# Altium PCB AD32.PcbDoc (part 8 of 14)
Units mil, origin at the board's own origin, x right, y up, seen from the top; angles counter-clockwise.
Board outline 7007.87 x 4368.85 mil, 12 copper layers (Top Layer, Int1 (GND), Int2 (AVDD), Int3 (DVDD), Int4 (GND), Int5 (ST), Int6 (SB), Int8 (AGND), Int7 (AVCC), Int9 (VCCA), Int10 (GND), Bottom Layer), stack 60.136 mil thick; 1350 components, 880 nets, 4712 pads, 2835 vias.
Unrouted connection lines stored in the file: 19.
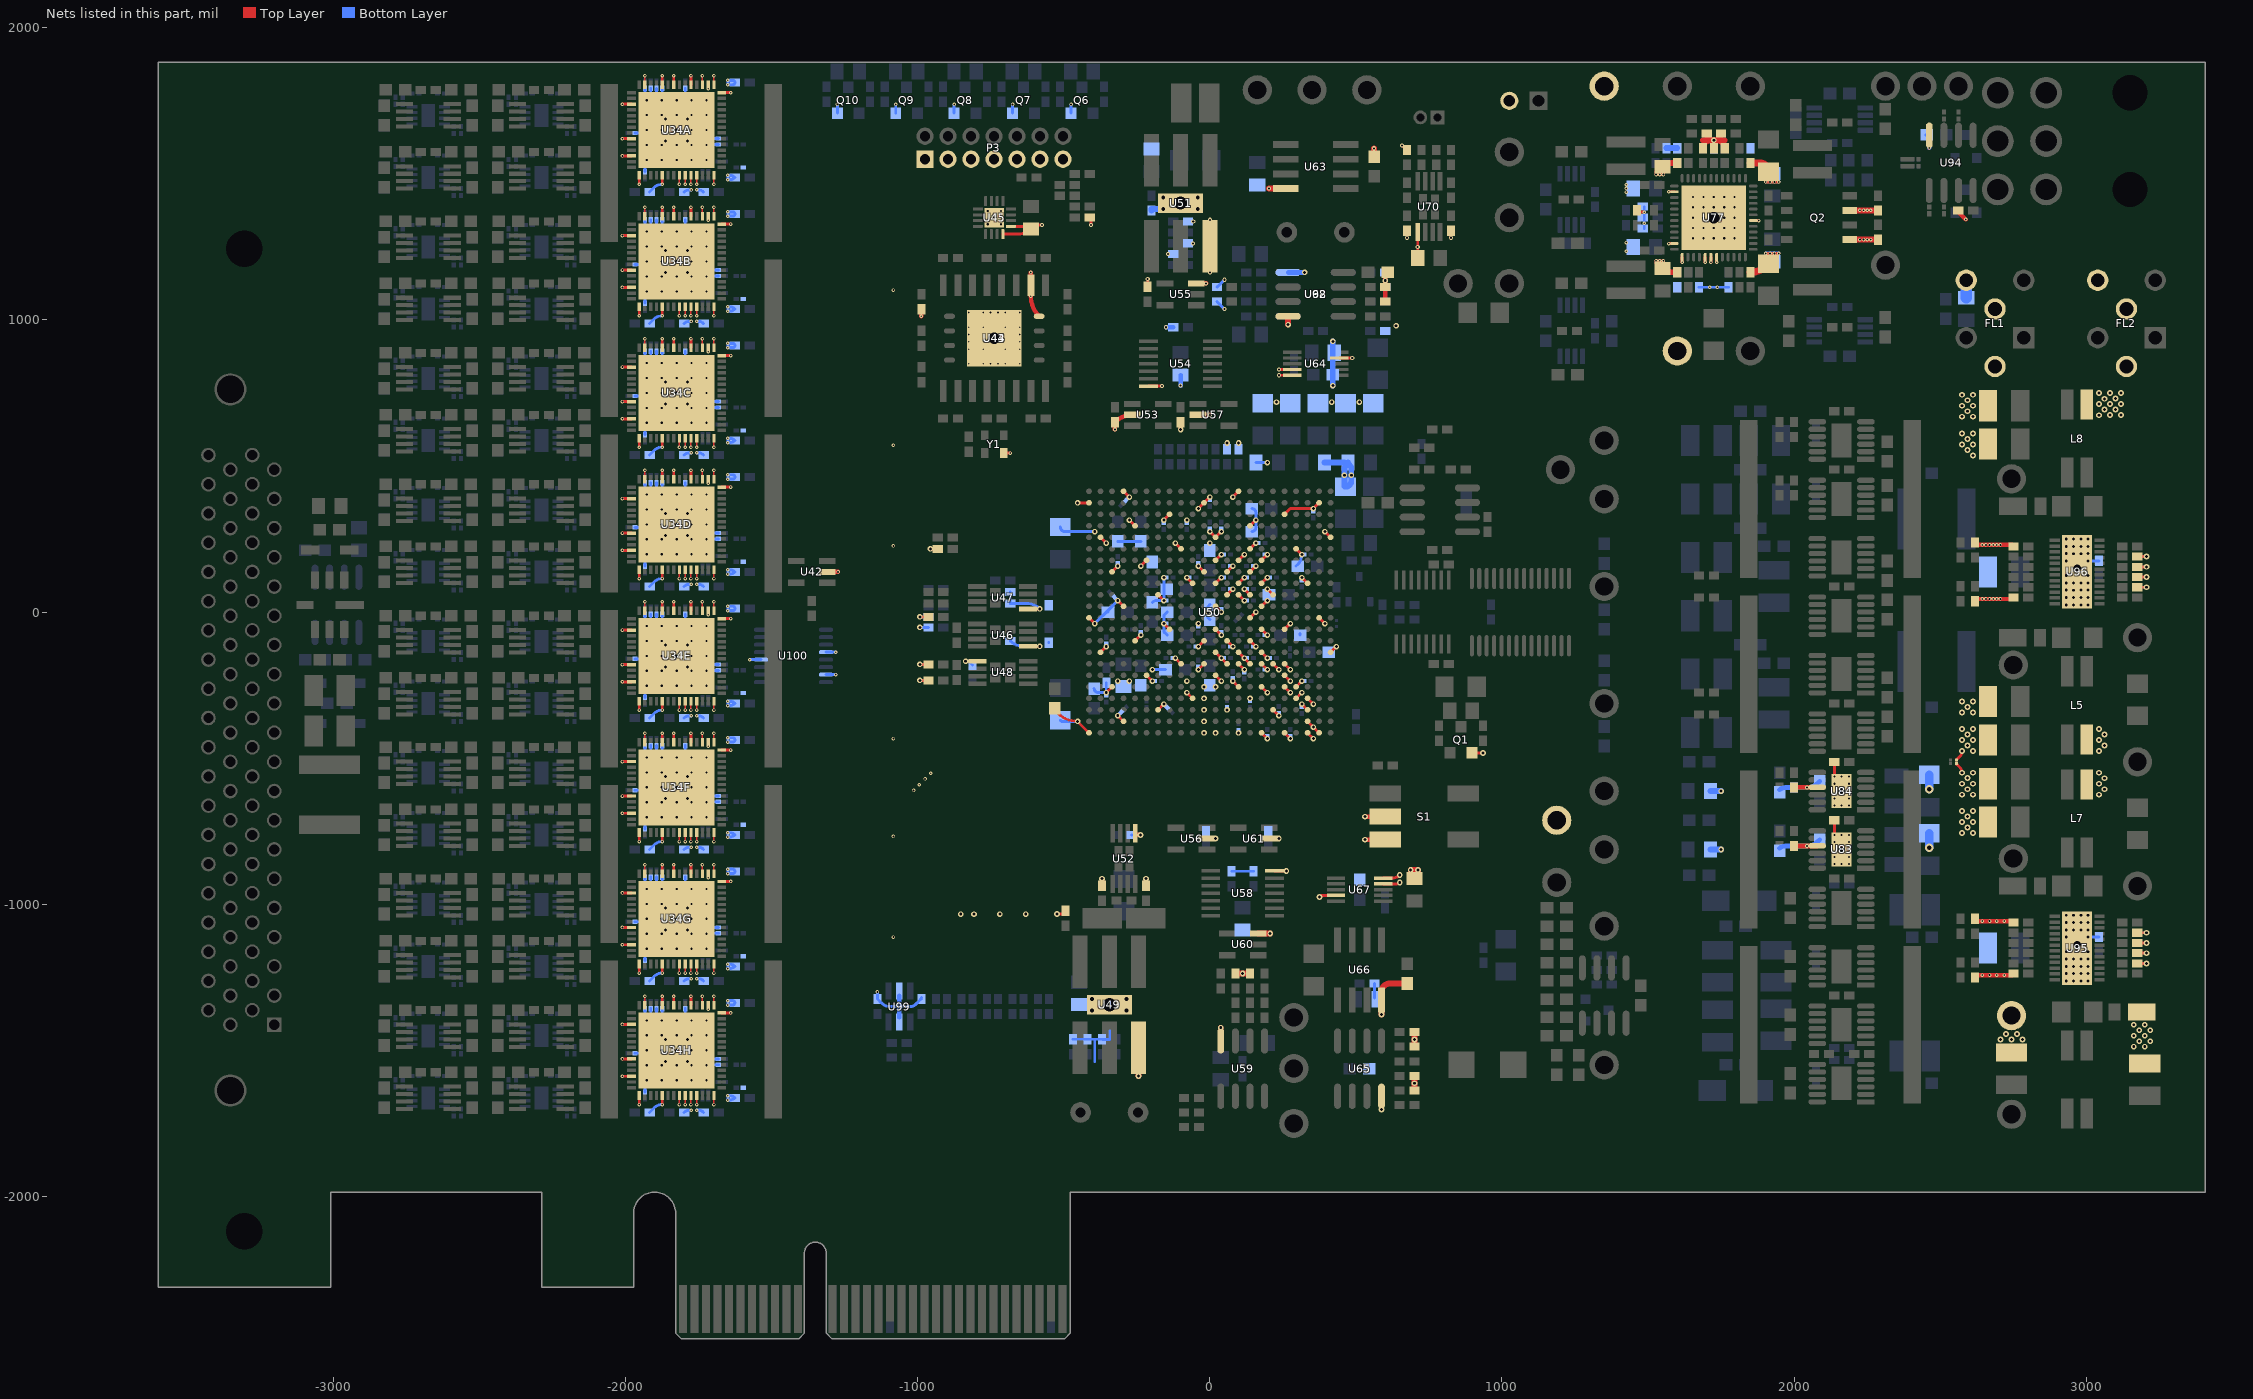
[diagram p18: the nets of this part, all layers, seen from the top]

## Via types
v1: diameter 12, hole 6, Top Layer to Bottom Layer, tented both sides, 1497 vias
v2: diameter 20, hole 10, Top Layer to Bottom Layer, tented both sides, 364 vias
v3: diameter 19, hole 10, Top Layer to Bottom Layer, tented both sides, 347 vias
v4: diameter 14, hole 7, Top Layer to Bottom Layer, tented both sides, 228 vias
v5: diameter 19.68, hole 7.87, Top Layer to Bottom Layer, 225 vias
v6: diameter 19.02, hole 10, Top Layer to Bottom Layer, tented both sides, 85 vias
v7: diameter 20, hole 10, Top Layer to Bottom Layer, 32 vias
v8: diameter 40, hole 20, Top Layer to Bottom Layer, tented both sides, 14 vias
v9: diameter 30, hole 15, Top Layer to Bottom Layer, tented both sides, 12 vias
v10: diameter 25, hole 13, Top Layer to Bottom Layer, 8 vias
v11: diameter 40, hole 20, Top Layer to Bottom Layer, 6 vias
v12: diameter 50, hole 20, Top Layer to Bottom Layer, 6 vias
v13: diameter 66, hole 47, Top Layer to Bottom Layer, tented both sides, 3 vias
v14: diameter 63, hole 45, Top Layer to Bottom Layer, 2 vias
v15: diameter 50, hole 25, Top Layer to Bottom Layer, 2 vias
v16: diameter 12, hole 6, Top Layer to Bottom Layer, 2 vias
v17: diameter 60, hole 40, Top Layer to Bottom Layer, tented both sides, 1 vias
v18: diameter 60, hole 40, Top Layer to Bottom Layer, 1 vias

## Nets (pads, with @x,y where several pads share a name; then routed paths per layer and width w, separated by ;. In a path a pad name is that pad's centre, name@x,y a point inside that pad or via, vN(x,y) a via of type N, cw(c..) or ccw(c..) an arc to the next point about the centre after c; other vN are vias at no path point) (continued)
GND: C5.2 C37.1 C39.1 C40.1 C41.1 C42.1 C44.1 C45.2 C47.1 C48.1 C49.1 C50.1 C51.1 C52.1 C53.1 C54.2 C55.1 C61.1 C64.1 C68.1 C69.1 C70.1 C71.1 C72.2 C73.1 C74.1 C75.1 C76.2 C77.1 C82.2 C83.1 C84.2 C85.1 C86.1 C87.2 C88.1 C89.1 C90.2 C91.2 C92.2 C93.2 C94.2 C95.1 C96.1 C101.1 C102.1 C103.2 C104.2 C105.1 C106.2 C107.2 C110.2 C111.2 C114.1 C115.1 C118.1 C119.1 C124.1 C125.1 C126.2 C127.2 C136.1 C137.2 C138.2 C139.2 C140.1 C148.1 C149.1 C150.1 C152.2 C153.1 C155.2 C156.1 C157.1 C159.1 C160.1 C161.1 C162.2 C164.1 C165.2 C166.1 C167.1 C168.1 C169.1 C170.1 C171.1 C172.2 C173.1 C174.1 C175.1 C176.1 C177.2 C178.2 C179.1 C180.1 C182.1 C183.1 C184.2 C185.1 C187.1 C188.2 C189.2 C190.1 C191.1 C193.2 C194.2 C195.2 C196.2 C197.2 C198.2 C199.2 C200.1 C201.1 C202.2 C203.2 C206.1 C207.1 C208.1 C209.2 C210.2 C211.2 C212.1 C213.1 C214.2 C215.2 C216.1 C217.1 C218.2 C219.2 C220.1 C222.1 C223.1 C224.1 C225.1 C226.1 C227.1 C228.1 C229.1 C230.1 C231.1 C232.1 C233.1 C234.1 C235.1 C236.1 C237.1 C238.1 C239.1 C240.1 C241.2 C242.1 C243.1 C244.1 C245.1 C246.1 C247.1 C248.2 C249.1 C250.1 C251.1 C252.1 C253.1 C254.1 C255.1 C256.1 C257.1 C258.1 C259.1 C260.1 C261.1 C262.2 C263.1 C264.2 C265.1 C266.1 C267.1 C268.1 C269.2 C270.1 C271.1 C272.1 C274.1 C275.1 C282.1 C285.1 C287.2 C288A.2 C288B.2 C288C.2 C288D.2 C288E.2 C288F.2 C288G.2 C288H.2 C289A.2 C289B.2 C289C.2 C289D.2 C289E.2 C289F.2 C289G.2 C289H.2 C304A.2 C304B.2 C304C.2 C304D.2 C304E.2 C304F.2 C304G.2 C304H.2 C312A.2 C312B.2 C312C.2 C312D.2 C312E.2 C312F.2 C312G.2 C312H.2 C320A.2 C320B.2 C320C.2 C320D.2 C320E.2 C320F.2 C320G.2 C320H.2 C328A.2 C328B.2 C328C.2 C328D.2 C328E.2 C328F.2 C328G.2 C328H.2 C336A.2 C336B.2 C336C.2 C336D.2 C336E.2 C336F.2 C336G.2 C336H.2 C344A.2 C344B.2 C344C.2 C344D.2 C344E.2 C344F.2 C344G.2 C344H.2 C352A.2 C352B.2 C352C.2 C352D.2 C352E.2 C352F.2 C352G.2 C352H.2 C360A.2 C360B.2 C360C.2 C360D.2 C360E.2 C360F.2 C360G.2 C360H.2 C361A.2 C361B.2 C361C.2 C361D.2 C361E.2 C361F.2 C361G.2 C361H.2 C383A.1 C383B.1 C383C.1 C383D.1 C383E.1 C383F.1 C383G.1 C383H.1 D8.2 FL1.4 FL1.5 FL1.6 FL2.4 FL2.5 FL2.6 FR10.1 L5.4 L7.3 L8.3 P3.1 P3.3 P3.5 P3.7 P3.9 P3.11 P3.13 P4.2 Q1.2 Q2.1 Q2.3 Q6.2 Q7.2 Q8.2 Q9.2 Q10.2 R135.2 R136.2 R137.1 R138.2 R139.2 R162.1 R165.1 R167.2 R179.2 R182.2 R183.2 R185.2 R219.2 R225.2 R227.2 R241.1 R242.1 R253.1 R254.1 R258.2 R259.2 R285.1 R286.1 R288.2 R291.2 R293.2 R294.2 R295.1 R314.1 R315.1 R324.1 R329.2 R331.2 R336.2 R339.1 R340.1 R341.1 R342.1 R343.2 R365.2 R366.2 R368.2 R376.2 R377.2 R383.2 R384.2 R386.1 R392.2 R395.1 R401A.2 R401B.2 R401C.2 R401D.2 R401E.2 R401F.2 R401G.2 R401H.2 R418A.1 R418B.1 R418C.1 R418D.1 R418E.1 R418F.1 R418G.1 R418H.1 R419A.1 R419B.1 R419C.1 R419D.1 R419E.1 R419F.1 R419G.1 R419H.1 S1.3 S1.5 TP14.1 TP24.1 TP25.1 TP34.1 U34A.14 U34A.15 U34A.16 U34A.17 U34A.19 U34A.22 U34A.24 U34A.27 U34A.31 U34A.37 U34A.40 U34A.43 U34A.47 U34A.50 U34A.51 U34A.52 U34A.53 U34A.56 U34A.57 U34B.14 U34B.15 U34B.16 U34B.17 U34B.19 U34B.22 U34B.24 U34B.27 U34B.31 U34B.37 U34B.40 U34B.43 U34B.47 U34B.50 U34B.51 U34B.52 U34B.53 U34B.56 U34B.57 U34C.14 U34C.15 U34C.16 U34C.17 U34C.19 U34C.22 U34C.24 U34C.27 U34C.31 U34C.37 U34C.40 U34C.43 U34C.47 U34C.50 U34C.51 U34C.52 U34C.53 U34C.56 U34C.57 U34D.14 U34D.15 U34D.16 U34D.17 U34D.19 U34D.22 U34D.24 U34D.27 U34D.31 U34D.37 U34D.40 U34D.43 U34D.47 U34D.50 U34D.51 U34D.52 U34D.53 U34D.56 U34D.57 U34E.14 U34E.15 U34E.16 U34E.17 U34E.19 U34E.22 U34E.24 U34E.27 U34E.31 U34E.37 U34E.40 U34E.43 U34E.47 U34E.50 U34E.51 U34E.52 U34E.53 U34E.56 U34E.57 U34F.14 U34F.15 U34F.16 U34F.17 U34F.19 U34F.22 U34F.24 U34F.27 U34F.31 U34F.37 U34F.40 U34F.43 U34F.47 U34F.50 U34F.51 U34F.52 U34F.53 U34F.56 U34F.57 U34G.14 U34G.15 U34G.16 U34G.17 U34G.19 U34G.22 U34G.24 U34G.27 U34G.31 U34G.37 U34G.40 U34G.43 U34G.47 U34G.50 U34G.51 U34G.52 U34G.53 U34G.56 U34G.57 U34H.14 U34H.15 U34H.16 U34H.17 U34H.19 U34H.22 U34H.24 U34H.27 U34H.31 U34H.37 U34H.40 U34H.43 U34H.47 U34H.50 U34H.51 U34H.52 U34H.53 U34H.56 U34H.57 U42.2 U43.10 U44.4 U44.9 U45.1 U45.16 U45.17 U45.18 U45.19 U45.20 U45.21 U45.22 U46.5 U47.5 U48.5 U49.3 U49.7 U50.A2 U50.A3 U50.A5 U50.A7 U50.A9 U50.A11 U50.A12 U50.A22 U50.AA2 U50.AA12 U50.AA22 U50.AB9 U50.AB19 U50.B3 U50.B12 U50.B19 U50.C3 U50.C6 U50.C10 U50.C12 U50.C16 U50.D3 U50.D4 U50.D8 U50.D12 U50.D13 U50.E4 U50.E5 U50.E7 U50.E9 U50.E11 U50.E12 U50.E20 U50.F5 U50.F11 U50.F17 U50.G5 U50.G6 U50.G7 U50.G8 U50.G9 U50.G10 U50.G12 U50.G14 U50.H1 U50.H7 U50.H9 U50.H11 U50.H21 U50.J8 U50.J10 U50.J12 U50.J18 U50.K5 U50.K7 U50.K11 U50.K15 U50.L2 U50.L8 U50.L22 U50.M7 U50.M11 U50.M19 U50.N6 U50.N8 U50.N9 U50.N10 U50.N16 U50.P3 U50.P7 U50.P9 U50.P11 U50.P13 U50.R8 U50.R10 U50.R12 U50.R20 U50.T7 U50.T9 U50.T11 U50.T17 U50.U4 U50.U8 U50.U14 U50.V1 U50.V11 U50.V21 U50.W8 U50.W18 U50.Y5 U50.Y15 U51.3 U51.7 U52.5 U53.2 U54.7 U55.3 U56.2 U57.2 U58.7 U59.4 U60.3 U61.2 U62.4 U63.4 U64.4 U64.5 U64.9 U65.4 U66.4 U67.4 U67.5 U67.9 U70.5 U77.2 U77.11 U77.13 U77.17 U77.18 U77.19 U77.30 U77.49 U83.9 U83.13 U84.9 U84.13 U94.4 U95.25 U96.25 U98.4 U99.2 U99.5 U100.4 U100.7 U100.12 W1.1 W2.1 Y1.2 | length 34851.7
  Top Layer w5: U34H.27@-1933.27,-1345.38 v1(-1933.27,-1314.57) ; U34G.27@-1933.27,-895.38 v1(-1933.27,-864.57) ; U34F.27@-1933.27,-445.38 v1(-1933.27,-414.57) ; U34E.27@-1933.27,4.62 v1(-1933.27,35.43) ; U34D.27@-1933.27,454.62 v1(-1933.27,485.43) ; U34C.27@-1933.27,904.62 v1(-1933.27,935.43) ; U34B.27@-1933.27,1354.62 v1(-1933.27,1385.43) ; U34A.27@-1933.27,1804.62 v1(-1933.27,1835.43) ; v1(-1815.16,-1685.43) U34H.50@-1815.16,-1654.62 ; v1(-1815.16,-1235.43) U34G.50@-1815.16,-1204.62 ; v1(-1815.16,-785.43) U34F.50@-1815.16,-754.62 ; v1(-1815.16,-335.43) U34E.50@-1815.16,-304.62 ; v1(-1815.16,114.57) U34D.50@-1815.16,145.38 ; v1(-1815.16,564.57) U34C.50@-1815.16,595.38 ; v1(-1815.16,1014.57) U34B.50@-1815.16,1045.38 ; v1(-1815.16,1464.57) U34A.50@-1815.16,1495.38 ; v1(-1795.47,-1685.43) U34H.51@-1795.47,-1654.62 ; v1(-1795.47,-1235.43) U34G.51@-1795.47,-1204.62 ; v1(-1795.47,-785.43) U34F.51@-1795.47,-754.62 ; v1(-1795.47,-335.43) U34E.51@-1795.47,-304.62 ; v1(-1795.47,114.57) U34D.51@-1795.47,145.38 ; v1(-1795.47,564.57) U34C.51@-1795.47,595.38 ; v1(-1795.47,1014.57) U34B.51@-1795.47,1045.38 ; v1(-1795.47,1464.57) U34A.51@-1795.47,1495.38 ; v1(-1775.79,-1685.43) U34H.52@-1775.79,-1654.62 ; v1(-1775.79,-1235.43) U34G.52@-1775.79,-1204.62 ; v1(-1775.79,-785.43) U34F.52@-1775.79,-754.62 ; v1(-1775.79,-335.43) U34E.52@-1775.79,-304.62 ; v1(-1775.79,114.57) U34D.52@-1775.79,145.38 ; v1(-1775.79,564.57) U34C.52@-1775.79,595.38 ; v1(-1775.79,1014.57) U34B.52@-1775.79,1045.38 ; v1(-1775.79,1464.57) U34A.52@-1775.79,1495.38 ; v1(-1756.1,-1685.43) U34H.53@-1756.1,-1654.62 ; v1(-1756.1,-1235.43) U34G.53@-1756.1,-1204.62 ; v1(-1756.1,-785.43) U34F.53@-1756.1,-754.62 ; v1(-1756.1,-335.43) U34E.53@-1756.1,-304.62 ; v1(-1756.1,114.57) U34D.53@-1756.1,145.38 ; v1(-1756.1,564.57) U34C.53@-1756.1,595.38 ; v1(-1756.1,1014.57) U34B.53@-1756.1,1045.38 ; v1(-1756.1,1464.57) U34A.53@-1756.1,1495.38 ; U34H.17@-1736.42,-1345.38 v1(-1736.42,-1314.57) ; U34G.17@-1736.42,-895.38 v1(-1736.42,-864.57) ; U34F.17@-1736.42,-445.38 v1(-1736.42,-414.57) ; U34E.17@-1736.42,4.62 v1(-1736.42,35.43) ; U34D.17@-1736.42,454.62 v1(-1736.42,485.43) ; U34C.17@-1736.42,904.62 v1(-1736.42,935.43) ; U34B.17@-1736.42,1354.62 v1(-1736.42,1385.43) ; U34A.17@-1736.42,1804.62 v1(-1736.42,1835.43) ; v1(-1697.05,-1685.43) U34H.56@-1697.05,-1654.62 ; U34H.15@-1697.05,-1345.38 v1(-1697.05,-1314.57) ; v1(-1697.05,-1235.43) U34G.56@-1697.05,-1204.62 ; U34G.15@-1697.05,-895.38 v1(-1697.05,-864.57) ; v1(-1697.05,-785.43) U34F.56@-1697.05,-754.62 ; U34F.15@-1697.05,-445.38 v1(-1697.05,-414.57) ; v1(-1697.05,-335.43) U34E.56@-1697.05,-304.62 ; U34E.15@-1697.05,4.62 v1(-1697.05,35.43) ; v1(-1697.05,114.57) U34D.56@-1697.05,145.38 ; U34D.15@-1697.05,454.62 v1(-1697.05,485.43) ; v1(-1697.05,564.57) U34C.56@-1697.05,595.38 ; U34C.15@-1697.05,904.62 v1(-1697.05,935.43) ; v1(-1697.05,1014.57) U34B.56@-1697.05,1045.38 ; U34B.15@-1697.05,1354.62 v1(-1697.05,1385.43) ; v1(-1697.05,1464.57) U34A.56@-1697.05,1495.38 ; U34A.15@-1697.05,1804.62 v1(-1697.05,1835.43)
  Top Layer w8: v4(675,1281.25) R183.2@675,1305.66 ; U70.5@711.61,1301.08 711.61,1223.67 ccw(c716.54,1223.67) C55.1@716.54,1218.75 ; v4(825,1281.25) C61.1@825,1305.66
  Top Layer w10: v1(-2010.43,-1588.58) U34H.40@-1979.62,-1588.58 ; v1(-2010.43,-1529.53) U34H.37@-1979.62,-1529.53 ; v1(-2010.43,-1411.42) U34H.31@-1979.62,-1411.42 ; v1(-2010.43,-1138.58) U34G.40@-1979.62,-1138.58 ; v1(-2010.43,-1079.53) U34G.37@-1979.62,-1079.53 ; v1(-2010.43,-961.42) U34G.31@-1979.62,-961.42 ; v1(-2010.43,-688.58) U34F.40@-1979.62,-688.58 ; v1(-2010.43,-629.53) U34F.37@-1979.62,-629.53 ; v1(-2010.43,-511.42) U34F.31@-1979.62,-511.42 ; v1(-2010.43,-238.58) U34E.40@-1979.62,-238.58 ; v1(-2010.43,-179.53) U34E.37@-1979.62,-179.53 ; v1(-2010.43,-61.42) U34E.31@-1979.62,-61.42 ; v1(-2010.43,211.42) U34D.40@-1979.62,211.42 ; v1(-2010.43,270.47) U34D.37@-1979.62,270.47 ; v1(-2010.43,388.58) U34D.31@-1979.62,388.58 ; v1(-2010.43,661.42) U34C.40@-1979.62,661.42 ; v1(-2010.43,720.47) U34C.37@-1979.62,720.47 ; v1(-2010.43,838.58) U34C.31@-1979.62,838.58 ; v1(-2010.43,1111.42) U34B.40@-1979.62,1111.42 ; v1(-2010.43,1170.47) U34B.37@-1979.62,1170.47 ; v1(-2010.43,1288.58) U34B.31@-1979.62,1288.58 ; v1(-2010.43,1561.42) U34A.40@-1979.62,1561.42 ; v1(-2010.43,1620.47) U34A.37@-1979.62,1620.47 ; v1(-2010.43,1738.58) U34A.31@-1979.62,1738.58 ; v1(-1952.95,-1685.43) U34H.43@-1952.95,-1654.62 ; v1(-1952.95,-1235.43) U34G.43@-1952.95,-1204.62 ; v1(-1952.95,-785.43) U34F.43@-1952.95,-754.62 ; v1(-1952.95,-335.43) U34E.43@-1952.95,-304.62 ; v1(-1952.95,114.57) U34D.43@-1952.95,145.38 ; v1(-1952.95,564.57) U34C.43@-1952.95,595.38 ; v1(-1952.95,1014.57) U34B.43@-1952.95,1045.38 ; v1(-1952.95,1464.57) U34A.43@-1952.95,1495.38 ; v1(-1874.21,-1685.43) U34H.47@-1874.21,-1654.62 ; U34H.24@-1874.21,-1345.38 v1(-1874.21,-1314.57) ; v1(-1874.21,-1235.43) U34G.47@-1874.21,-1204.62 ; U34G.24@-1874.21,-895.38 v1(-1874.21,-864.57) ; v1(-1874.21,-785.43) U34F.47@-1874.21,-754.62 ; U34F.24@-1874.21,-445.38 v1(-1874.21,-414.57) ; v1(-1874.21,-335.43) U34E.47@-1874.21,-304.62 ; U34E.24@-1874.21,4.62 v1(-1874.21,35.43) ; v1(-1874.21,114.57) U34D.47@-1874.21,145.38 ; U34D.24@-1874.21,454.62 v1(-1874.21,485.43) ; v1(-1874.21,564.57) U34C.47@-1874.21,595.38 ; U34C.24@-1874.21,904.62 v1(-1874.21,935.43) ; v1(-1874.21,1014.57) U34B.47@-1874.21,1045.38 ; U34B.24@-1874.21,1354.62 v1(-1874.21,1385.43) ; v1(-1874.21,1464.57) U34A.47@-1874.21,1495.38 ; U34A.24@-1874.21,1804.62 v1(-1874.21,1835.43) ; U34H.22@-1834.84,-1345.38 v1(-1834.84,-1314.57) ; U34G.22@-1834.84,-895.38 v1(-1834.84,-864.57) ; U34F.22@-1834.84,-445.38 v1(-1834.84,-414.57) ; U34E.22@-1834.84,4.62 v1(-1834.84,35.43) ; U34D.22@-1834.84,454.62 v1(-1834.84,485.43) ; U34C.22@-1834.84,904.62 v1(-1834.84,935.43) ; U34B.22@-1834.84,1354.62 v1(-1834.84,1385.43) ; U34A.22@-1834.84,1804.62 v1(-1834.84,1835.43) ; U34H.19@-1775.79,-1345.38 v1(-1775.79,-1314.57) ; U34G.19@-1775.79,-895.38 v1(-1775.79,-864.57) ; U34F.19@-1775.79,-445.38 v1(-1775.79,-414.57) ; U34E.19@-1775.79,4.62 v1(-1775.79,35.43) ; U34D.19@-1775.79,454.62 v1(-1775.79,485.43) ; U34C.19@-1775.79,904.62 v1(-1775.79,935.43) ; U34B.19@-1775.79,1354.62 v1(-1775.79,1385.43) ; U34A.19@-1775.79,1804.62 v1(-1775.79,1835.43) ; U34H.14@-1670.38,-1372.05 v1(-1639.57,-1372.05) ; U34G.14@-1670.38,-922.05 v1(-1639.57,-922.05) ; U34F.14@-1670.38,-472.05 v1(-1639.57,-472.05) ; U34E.14@-1670.38,-22.05 v1(-1639.57,-22.05) ; U34D.14@-1670.38,427.95 v1(-1639.57,427.95) ; U34C.14@-1670.38,877.95 v1(-1639.57,877.95) ; U34B.14@-1670.38,1327.95 v1(-1639.57,1327.95) ; U34A.14@-1670.38,1777.95 v1(-1639.57,1777.95) ; v3(-992.5,-233.9) R137.1@-963.09,-233.9 ; v3(-992.5,-178.9) R136.2@-963.09,-178.9 ; v3(-992.5,-16.3) R138.2@-963.07,-16.3 ; v3(-956.69,216.54) R139.2@-931.1,216.54 ; v3(-835.96,-168.31) U48.5@-795.08,-168.31 ; U45.16@-707.97,1293.5 -656.22,1293.5 ccw(c-656.22,1355.34) C37.1@-612.5,1311.61 ; Y1.2@-705.02,544.29 v1(-683.07,544.29) ; U45.1@-681,1320.47 -633.89,1320.47 cw(c-633.89,1290.23) C37.1@-612.5,1311.61 ; U46.5@-622.24,-117.13 v3(-582.07,-117.13) ; U47.5@-622.24,10.83 v3(-582.07,10.83) ; v4(-575,1325) -580.18,1325 ccw(c-580.18,1279.3) C37.1@-612.5,1311.61 ; C249.1@-531.5,-334.65 -519.97,-346.18 ccw(c-452.76,-278.97) v3(-452.76,-374.02) U50.A22@-413.39,-413.39 ; v2(-523.35,-1033.46) -505.31,-1033.46 ccw(c-505.31,-1021.91) C39.1@-493.75,-1021.91 ; v3(-452.76,374.02) U50.AA22@-413.39,374.02 ; U50.L22@-413.39,-19.68 v3(-393.7,-39.37) ; C5.2@-410.66,1350 cw(c-420.88,1339.78) -406.43,1339.78 v4(-406.43,1325.06) ; U50.H21@-374.02,-137.8 v3(-354.33,-118.11) ; U50.V21@-374.02,255.91 v3(-354.33,236.22) ; v3(-354.33,-275.59) U50.E20@-334.65,-255.91 ; U50.R20@-334.65,137.8 v3(-314.96,157.48) ; v3(-314.96,-354.33) U50.B19@-295.28,-374.02 ; v3(-314.96,39.37) U50.M19@-295.28,19.69 ; U50.AB19@-295.28,413.39 v3(-275.59,393.7) ; v3(-275.59,314.96) U50.W18@-255.91,295.28 ; U50.J18@-255.91,-98.43 v3(-236.22,-78.74) ; v3(-236.22,157.48) U50.T17@-216.54,177.17 ; U50.F17@-216.54,-216.54 v3(-196.85,-236.22) ; C41.1@-212.5,1113.09 v4(-212.5,1140) ; U54.7@-209.25,773.23 v4(-164.27,773.23) ; U50.C16@-177.17,-334.65 v3(-157.48,-314.96) ; U50.N16@-177.17,59.06 v3(-157.48,39.37) ; v3(-157.48,-39.37) U50.K15@-137.8,-59.06 ; v3(-157.48,314.96) U50.Y15@-137.8,334.65 ; v3(-118.11,-157.48) U50.G14@-98.43,-177.17 ; v3(-118.11,236.22) U50.U14@-98.43,216.54 ; v3(-78.74,-275.59) U50.D13@-59.05,-295.28 ; v3(-78.74,118.11) U50.P13@-59.05,98.43 ; v3(-39.37,-196.85) U50.G12@-19.68,-177.17 ; v3(-39.37,-118.11) U50.J12@-19.68,-98.43 ; v3(-39.37,157.48) U50.R12@-19.68,137.8 ; v3(-39.37,354.33) U50.AA12@-19.68,374.02 v3(0,393.7) ; v3(0,275.59) U50.V11@19.69,255.91 v3(39.37,275.59) ; U50.F11@19.69,-216.54 v3(39.37,-236.22) ; U50.H11@19.69,-137.8 v3(39.37,-157.48) U50.G10@59.06,-177.17 ; U50.K11@19.69,-59.06 v3(39.37,-78.74) ; U50.M11@19.69,19.69 v3(39.37,0) ; U50.P11@19.69,98.43 v3(39.37,118.11) ; U50.T11@19.69,177.17 v3(39.37,196.85) ; U50.J10@59.06,-98.43 v3(78.74,-118.11) ; U50.N10@59.06,59.06 v3(78.74,78.74) ; U50.R10@59.06,137.8 v3(78.74,157.48) ; v3(78.74,-236.22) U50.E9@98.43,-255.91 ; v3(78.74,393.7) U50.AB9@98.43,413.39 ; U50.G9@98.43,-177.17 v3(118.11,-196.85) ; U50.H9@98.43,-137.8 v3(118.11,-157.48) U50.G8@137.8,-177.17 ; U50.N9@98.43,59.06 v3(118.11,39.37) ; U50.P9@98.43,98.43 v3(118.11,118.11) ; U50.T9@98.43,177.17 v3(118.11,196.85) ; v3(118.11,78.74) U50.N8@137.8,59.06 ; U50.J8@137.8,-98.43 v3(157.48,-118.11) ; U50.L8@137.8,-19.68 v3(157.48,0) ; U50.R8@137.8,137.8 v3(157.48,157.48) ; U50.U8@137.8,216.54 v3(157.48,236.22) ; U50.W8@137.8,295.28 v3(157.48,314.96) ; U50.A7@177.17,-413.39 v3(196.85,-433.07) ; U50.E7@177.17,-255.91 v3(196.85,-275.59) ; U50.G7@177.17,-177.17 v3(196.85,-196.85) ; U50.H7@177.17,-137.8 v3(196.85,-157.48) ; U50.K7@177.17,-59.06 v3(196.85,-78.74) ; U50.M7@177.17,19.69 v3(196.85,39.37) ; U50.P7@177.17,98.43 v3(196.85,118.11) ; U50.T7@177.17,177.17 v3(196.85,196.85) ; v3(196.85,78.74) U50.N6@216.54,59.06 ; U50.C6@216.54,-334.65 v3(236.22,-354.33) ; U50.G6@216.54,-177.17 v3(236.22,-196.85) ; v4(237.5,810.63) U64.5@281.79,810.63 ; v4(237.5,830.32) U64.4@281.79,830.32 ; U50.A5@255.91,-413.39 v3(275.59,-433.07) ; U50.E5@255.91,-255.91 v3(275.59,-275.59) ; U50.F5@255.91,-216.54 v3(275.59,-236.22) ; U50.G5@255.91,-177.17 v3(275.59,-196.85) ; U50.K5@255.91,-59.06 v3(275.59,-39.37) ; U50.Y5@255.91,334.65 275.59,354.33 v3(354.33,354.33) U50.AA2@374.02,374.02 ; U50.D4@295.28,-295.28 v3(314.96,-275.59) ; U50.E4@295.28,-255.91 v3(314.96,-236.22) ; U50.U4@295.28,216.54 v3(314.96,196.85) ; v3(314.96,-314.96) U50.C3@334.65,-334.65 ; v3(314.96,118.11) U50.P3@334.65,98.43 ; U50.A3@334.65,-413.39 v3(354.33,-433.07) ; U50.B3@334.65,-374.02 v3(354.33,-393.7) U50.A2@374.02,-413.39 ; U50.D3@334.65,-295.28 v3(354.33,-314.96) ; U50.L2@374.02,-19.68 v3(393.7,-39.37) ; v2(375,-975) cw(c387.83,-987.83) 387.83,-969.68 U67.9@431.79,-969.68 ; v3(393.7,275.59) U50.V1@413.39,255.91 ; U50.H1@413.39,-137.8 v3(433.07,-118.11) ; U64.9@443.21,869.69 v4(487.5,869.69) ; U67.4@593.21,-930.31 637.17,-930.31 ccw(c637.17,-912.17) v2(650,-925) ; U67.5@593.21,-910.63 624.34,-910.63 ccw(c624.34,-874.34) v2(650,-900) ; v4(658.45,1597.36) R185.2@673.24,1582.57 ; R185.2@673.24,1582.57 ccw(c675,1584.33) R185.2@675,1581.84 ; Q1.2@897.4,-481.79 933.29,-481.79 cw(c933.29,-484.21) v2(935,-482.5) ; C64.1@1462.5,1375.59 ccw(c1478.55,1391.64) 1478.55,1368.94 v1(1486.91,1368.94) ; C68.1@1527.5,1192.5 v1(1527.5,1202.5) v1(1540,1202.5) v1(1552.5,1202.5) C68.1@1552.5,1195 ; C69.1@1527.5,1510 v1(1527.5,1497.5) v1(1540,1497.5) v1(1552.5,1497.5) 1552.5,1522.5 C69.1@1550,1522.5 ; v1(1571,1261.42) U77.11@1590.16,1261.42 ; v1(1571,1438.58) U77.2@1590.16,1438.58 ; v1(1616.73,1197.36) U77.13@1616.73,1215.16 ; v1(1695.47,1197.36) U77.17@1695.47,1215.16 ; v1(1715.16,1197.36) U77.18@1715.16,1215.16 ; v1(1734.84,1197.36) U77.19@1734.84,1215.16 ; U77.30@1859.84,1340.16 v1(1878.54,1340.16) ; v1(1902.5,1227.5) v1(1917.5,1227.5) v1(1932.5,1227.5) v1(1947.5,1227.5) ; v1(1902.5,1472.5) v1(1917.5,1472.5) 1925,1472.5 ; C76.2@1906.29,1186.41 1909.17,1189.29 ccw(c1870.97,1227.5) 1925,1227.5 ; C77.1@1912.5,1507.38 cw(c1882.32,1477.2) 1925,1477.2 1925,1472.5 ; v1(1947.5,1472.5) v1(1932.5,1472.5) 1925,1472.5 ; v4(2044.47,-800.59) 2078.55,-800.59 ccw(c2078.55,-799.7) U83.9@2079.44,-799.7 ; R253.1@2136.91,-712.5 cw(c2135.48,-713.93) 2137.5,-713.93 v4(2137.5,-762.2) ; R254.1@2136.91,-512.5 cw(c2135.48,-513.93) 2137.5,-513.93 v4(2137.5,-562.2) ; v1(2462.5,1588.68) U94.4@2462.5,1631.99 ; W1.1@2555,-518.75 2566.16,-529.91 cw(c2544.82,-551.25) v2@2575,-551.25 ; W2.1@2555,-506.25 2567.05,-494.2 ccw(c2547.84,-475) v2(2575,-475) ; R288.2@3174.34,-1202.5 v2(3206.25,-1202.5) ; C103.2@3174.34,-1167.5 v2(3206.25,-1167.5) ; C101.1@3174.34,-1132.5 v2(3206.25,-1132.5) ; R285.1@3174.34,-1097.5 v2(3206.25,-1097.5) ; R291.2@3174.34,85 v2(3206.25,85) ; C104.2@3174.34,120 v2(3206.25,120) ; C102.1@3174.34,155 v2(3206.25,155) ; R286.1@3174.34,190 v2(3206.25,190)
  Top Layer w12: U56.2@-9.35,-775 v2(19.69,-775) ; U61.2@203.15,-775 v2(236.22,-775) ; U58.7@221.75,-885.73 221.85,-885.83 v2(261.81,-885.83) ; v2(587.5,-1702.5) U65.4@587.5,-1656.99
  Top Layer w15: U42.2@-1309.35,137.5 v1(-1272.5,137.5) ; v1(-987.5,1012.5) R135.2@-987.5,1036.91 ; v1(-612.5,1162.5) U43.10@-612.5,1118.6 v1(-612.5,1081.41) ccw(c-515.04,1081.41) U44.4@-583.96,1012.5 ; R162.1@-368.75,-936.91 v2(-368.75,-912.5) ; v4(-325,625) C40.1@-325,649.41 -323.28,651.13 cw(c-265.65,593.5) U53.2@-265.65,675 ; U52.5@-255.36,-757.33 ccw(c-250.2,-757.33) -250.2,-762.5 v2(-237.5,-762.5) ; R167.2@-218.75,-936.91 v2(-218.75,-912.5) ; v6(-100,625) C42.1@-100,649.41 ; U55.3@-46.85,1124.9 -46.85,1125 v4(-12.5,1125) ; U57.2@-40.65,675 v4(0,675) ; v3(531.25,-778.74) S1.3@600,-778.74 ; v3(531.25,-700) S1.5@600,-700 ; U84.13@2136.91,-562.2 v4(2137.5,-562.2) ; C110.2@2561.91,1375 ccw(c2575.57,1375) 2565.91,1365.34 v1(2587.5,1343.75) ; C82.2@2618.75,-1250.59 cw(c2626.84,-1250.59) 2626.84,-1242.5 v1(2643.75,-1242.5) v1(2668.75,-1242.5) v1(2693.75,-1242.5) v1(2718.75,-1242.5) 2745.66,-1242.5 ccw(c2745.66,-1237.5) C93.2@2750.66,-1237.5 ; C83.1@2618.75,-1049.41 ccw(c2626.84,-1049.41) 2626.84,-1057.5 v1(2643.75,-1057.5) v1(2668.75,-1057.5) v1(2693.75,-1057.5) v1(2718.75,-1057.5) 2745.66,-1057.5 cw(c2745.66,-1062.5) C95.1@2750.66,-1062.5 ; C84.2@2618.75,36.91 cw(c2626.84,36.91) 2626.84,45 v1(2643.75,45) v1(2656.25,45) v1(2668.75,45) v1(2681.25,45) v1(2693.75,45) v1(2706.25,45) 2745.66,45 ccw(c2745.66,50) C94.2@2750.66,50 ; C85.1@2618.75,238.09 ccw(c2626.84,238.09) 2626.84,230 v1(2643.75,230) v1(2656.25,230) v1(2668.75,230) v1(2681.25,230) v1(2693.75,230) v1(2706.25,230) 2745.66,230 cw(c2745.66,225) C96.1@2750.66,225
  Top Layer w16: R179.2@600.59,1062.5 C47.1@600.59,1162.5 ; R241.1@2000,-800.59 2077.3,-800.59 ccw(c2077.3,-797.57) U83.9@2079.44,-799.7 ; R242.1@2000,-600.59 cw(c2002.14,-602.73) 2002.14,-599.7 v4(2044.47,-599.7) U84.9@2079.44,-599.7
  Top Layer w20: v2(-243.75,-1587.5) U49.3@-243.75,-1490.75 ; U59.4@37.5,-1468.01 v2(37.5,-1422.5) ; C44.1@87.5,-1236.91 C45.2@137.5,-1236.91 ; U60.3@165.65,-1100.1 v2(206.69,-1100.1) ; v4(202.51,1450) U63.4@260.14,1450 ; v3(268.01,984.01) U62.4@268.01,1012.5 ; C49.1@562.5,1558.46 v4(562.5,1587.5) ; v2(587.5,-1377.5) U66.4@587.5,-1327.36 587.5,-1300 cw(c616.54,-1300) 616.54,-1270.96 C53.1@675,-1270.96 ; C50.1@700.59,-1637.5 C51.1@700.59,-1587.5 ; R182.2@700.59,-1487.5 C52.1@700.59,-1437.5 ; C68.1@1550,1175.89 ccw(c1580.89,1206.78) 1580.89,1163.09 C70.1@1600,1163.09 ; C69.1@1550,1524.11 cw(c1580.89,1493.22) 1580.89,1536.91 C71.1@1600,1536.91 ; C72.2@1687.5,1588.09 cw(c1714.41,1588.09) 1714.41,1615 ; 1687.5,1615 1714.41,1615 ; R219.2@1700.59,1637.5 ccw(c1723.09,1637.5) v2@1723.09,1615 ; C73.1@1725,1588.09 v2(1725,1615) ; R225.2@1749.41,1637.5 cw(c1726.91,1637.5) v2@1726.91,1615 ; R227.2@1762.5,1588.09 ccw(c1735.59,1588.09) 1735.59,1615 ; 1762.5,1615 1735.59,1615 ; Q2.1@2190.16,1275 v1(2225,1275) v1(2237.5,1275) v1(2250,1275) v1(2262.5,1275) 2286.07,1275 cw(c2286.07,1272.98) R258.2@2287.5,1274.41 ; Q2.3@2190.16,1375 v1(2225,1375) v1(2237.5,1375) v1(2250,1375) v1(2262.5,1375) 2286.07,1375 cw(c2286.07,1372.98) R259.2@2287.5,1374.41 ; 1714.41,1615 v2@1723.09,1615 ; v2@1723.09,1615 v2(1725,1615) ; v2(1725,1615) v2@1726.91,1615 ; v2@1726.91,1615 1735.59,1615 ; v2(687.5,-882.5) ccw(c727.61,-882.5) 699.25,-910.86 C54.2@700,-911.61 700.75,-910.86 ccw(c672.39,-882.5) v2(712.5,-882.5) v2(687.5,-882.5)
  Top Layer w25: C74.1@1850,1163.09 ccw(c1850,1242.69) C76.2@1906.29,1186.41 ; C75.1@1850,1536.91 1882.97,1536.91 cw(c1882.97,1507.38) C77.1@1912.5,1507.38 C77.1@1906.29,1513.59 ; C76.2@1909.19,1189.31 C76.2@1912.5,1192.62
  Bottom Layer w10: C383H.1@-1967.69,-1509.84 -1927.36,-1509.84 ; C383G.1@-1967.69,-1059.84 -1927.36,-1059.84 ; C383F.1@-1967.69,-609.84 -1927.36,-609.84 ; C383E.1@-1967.69,-159.84 -1927.36,-159.84 ; C383D.1@-1967.69,290.16 -1927.36,290.16 ; C383C.1@-1967.69,740.16 -1927.36,740.16 ; C383B.1@-1967.69,1190.16 -1927.36,1190.16 ; C383A.1@-1967.69,1640.16 -1927.36,1640.16 ; C360H.2@-1933.27,-1642.69 -1933.27,-1608.27 v5(-1927.36,-1602.36) ; C361H.2@-1933.27,-1357.31 -1933.27,-1391.73 v5(-1927.36,-1397.64) ; C360G.2@-1933.27,-1192.69 -1933.27,-1158.27 v5(-1927.36,-1152.36) ; C361G.2@-1933.27,-907.31 -1933.27,-941.73 v5(-1927.36,-947.64) ; C360F.2@-1933.27,-742.69 -1933.27,-708.27 v5(-1927.36,-702.36) ; C361F.2@-1933.27,-457.31 -1933.27,-491.73 v5(-1927.36,-497.64) ; C360E.2@-1933.27,-292.69 -1933.27,-258.27 v5(-1927.36,-252.36) ; C361E.2@-1933.27,-7.31 -1933.27,-41.73 v5(-1927.36,-47.64) ; C360D.2@-1933.27,157.31 -1933.27,191.73 v5(-1927.36,197.64) ; C361D.2@-1933.27,442.69 -1933.27,408.27 v5(-1927.36,402.36) ; C360C.2@-1933.27,607.31 -1933.27,641.73 v5(-1927.36,647.64) ; C361C.2@-1933.27,892.69 -1933.27,858.27 v5(-1927.36,852.36) ; C360B.2@-1933.27,1057.31 -1933.27,1091.73 v5(-1927.36,1097.64) ; C361B.2@-1933.27,1342.69 -1933.27,1308.27 v5(-1927.36,1302.36) ; C360A.2@-1933.27,1507.31 -1933.27,1541.73 v5(-1927.36,1547.64) ; C361A.2@-1933.27,1792.69 -1933.27,1758.27 v5(-1927.36,1752.36) ; C344H.2@-1917.52,-1712.5 -1901.93,-1696.91 cw(c-1874.21,-1724.64) v1(-1874.21,-1685.43) ; C344G.2@-1917.52,-1262.5 -1901.93,-1246.91 cw(c-1874.21,-1274.64) v1(-1874.21,-1235.43) ; C344F.2@-1917.52,-812.5 -1901.93,-796.91 cw(c-1874.21,-824.64) v1(-1874.21,-785.43) ; C344E.2@-1917.52,-362.5 -1901.93,-346.91 cw(c-1874.21,-374.64) v1(-1874.21,-335.43) ; C344D.2@-1917.52,87.5 -1901.93,103.09 cw(c-1874.21,75.36) v1(-1874.21,114.57) ; C344C.2@-1917.52,537.5 -1901.93,553.09 cw(c-1874.21,525.36) v1(-1874.21,564.57) ; C344B.2@-1917.52,987.5 -1901.93,1003.09 cw(c-1874.21,975.36) v1(-1874.21,1014.57) ; C344A.2@-1917.52,1437.5 -1901.93,1453.09 cw(c-1874.21,1425.36) v1(-1874.21,1464.57) ; -1913.58,-1397.64 C352H.2@-1913.58,-1357.31 ; -1913.58,-947.64 C352G.2@-1913.58,-907.31 ; -1913.58,-497.64 C352F.2@-1913.58,-457.31 ; -1913.58,-47.64 C352E.2@-1913.58,-7.31 ; -1913.58,402.36 C352D.2@-1913.58,442.69 ; -1913.58,852.36 C352C.2@-1913.58,892.69 ; -1913.58,1302.36 C352B.2@-1913.58,1342.69 ; -1913.58,1752.36 C352A.2@-1913.58,1792.69 ; -1893.9,-1397.64 C336H.2@-1893.9,-1357.31 ; -1893.9,-947.64 C336G.2@-1893.9,-907.31 ; -1893.9,-497.64 C336F.2@-1893.9,-457.31 ; -1893.9,-47.64 C336E.2@-1893.9,-7.31 ; -1893.9,402.36 C336D.2@-1893.9,442.69 ; -1893.9,852.36 C336C.2@-1893.9,892.69 ; -1893.9,1302.36 C336B.2@-1893.9,1342.69 ; -1893.9,1752.36 C336A.2@-1893.9,1792.69 ; v5@-1874.21,-1397.64 C328H.2@-1874.21,-1357.31 ; v5@-1874.21,-947.64 C328G.2@-1874.21,-907.31 ; v5@-1874.21,-497.64 C328F.2@-1874.21,-457.31 ; v5@-1874.21,-47.64 C328E.2@-1874.21,-7.31 ; v5@-1874.21,402.36 C328D.2@-1874.21,442.69 ; v5@-1874.21,852.36 C328C.2@-1874.21,892.69 ; v5@-1874.21,1302.36 C328B.2@-1874.21,1342.69 ; v5@-1874.21,1752.36 C328A.2@-1874.21,1792.69 ; v5@-1825.27,-1602.36 v5@-1825.27,-1602.09 ; v5@-1825.27,-1152.36 v5@-1825.27,-1152.09 ; v5@-1825.27,-702.36 v5@-1825.27,-702.09 ; v5@-1825.27,-252.36 v5@-1825.27,-252.09 ; v5@-1825.27,197.64 v5@-1825.27,197.91 ; v5@-1825.27,647.64 v5@-1825.27,647.91 ; v5@-1825.27,1097.64 v5@-1825.27,1097.91 ; v5@-1825.27,1547.64 v5@-1825.27,1547.91 ; C312H.2@-1799.41,-1712.5 cw(c-1781.3,-1730.61) -1781.3,-1705 v1(-1775,-1705) ; C312G.2@-1799.41,-1262.5 cw(c-1781.3,-1280.61) -1781.3,-1255 v1(-1775,-1255) ; C312F.2@-1799.41,-812.5 cw(c-1781.3,-830.61) -1781.3,-805 v1(-1775,-805) ; C312E.2@-1799.41,-362.5 cw(c-1781.3,-380.61) -1781.3,-355 v1(-1775,-355) ; C312D.2@-1799.41,87.5 cw(c-1781.3,69.39) -1781.3,95 v1(-1775,95) ; C312C.2@-1799.41,537.5 cw(c-1781.3,519.39) -1781.3,545 v1(-1775,545) ; C312B.2@-1799.41,987.5 cw(c-1781.3,969.39) -1781.3,995 v1(-1775,995) ; C312A.2@-1799.41,1437.5 cw(c-1781.3,1419.39) -1781.3,1445 v1(-1775,1445) ; -1795.47,-1397.64 C320H.2@-1795.47,-1357.31 ; -1795.47,-947.64 C320G.2@-1795.47,-907.31 ; -1795.47,-497.64 C320F.2@-1795.47,-457.31 ; -1795.47,-47.64 C320E.2@-1795.47,-7.31 ; -1795.47,402.36 C320D.2@-1795.47,442.69 ; -1795.47,852.36 C320C.2@-1795.47,892.69 ; -1795.47,1302.36 C320B.2@-1795.47,1342.69 ; -1795.47,1752.36 C320A.2@-1795.47,1792.69 ; v1(-1756.1,-1704.76) -1751.17,-1704.76 cw(c-1751.17,-1731.19) C304H.2@-1732.48,-1712.5 ; v1(-1756.1,-1254.76) -1751.17,-1254.76 cw(c-1751.17,-1281.19) C304G.2@-1732.48,-1262.5 ; v1(-1756.1,-804.76) -1751.17,-804.76 cw(c-1751.17,-831.19) C304F.2@-1732.48,-812.5 ; v1(-1756.1,-354.76) -1751.17,-354.76 cw(c-1751.17,-381.19) C304E.2@-1732.48,-362.5 ; v1(-1756.1,95.24) -1751.17,95.24 cw(c-1751.17,68.81) C304D.2@-1732.48,87.5 ; v1(-1756.1,545.24) -1751.17,545.24 cw(c-1751.17,518.81) C304C.2@-1732.48,537.5 ; v1(-1756.1,995.24) -1751.17,995.24 cw(c-1751.17,968.81) C304B.2@-1732.48,987.5 ; v1(-1756.1,1445.24) -1751.17,1445.24 cw(c-1751.17,1418.81) C304A.2@-1732.48,1437.5 ; v5(-1722.64,-1602.36) v5@-1716.73,-1608.27 ; v5(-1722.64,-1551.18) v5@-1720.67,-1549.21 ; v5@-1722.64,-1549.21 v5@-1720.67,-1549.21 ; -1722.64,-1529.53 R419H.1@-1682.31,-1529.53 ; v5(-1722.64,-1152.36) v5@-1716.73,-1158.27 ; v5(-1722.64,-1101.18) v5@-1720.67,-1099.21 ; v5@-1722.64,-1099.21 v5@-1720.67,-1099.21 ; -1722.64,-1079.53 R419G.1@-1682.31,-1079.53 ; v5(-1722.64,-702.36) v5@-1716.73,-708.27 ; v5(-1722.64,-651.18) v5@-1720.67,-649.21 ; v5@-1722.64,-649.21 v5@-1720.67,-649.21 ; -1722.64,-629.53 R419F.1@-1682.31,-629.53 ; v5(-1722.64,-252.36) v5@-1716.73,-258.27 ; v5(-1722.64,-201.18) v5@-1720.67,-199.21 ; v5@-1722.64,-199.21 v5@-1720.67,-199.21 ; -1722.64,-179.53 R419E.1@-1682.31,-179.53 ; v5(-1722.64,197.64) v5@-1716.73,191.73 ; v5(-1722.64,248.82) v5@-1720.67,250.79 ; v5@-1722.64,250.79 v5@-1720.67,250.79 ; -1722.64,270.47 R419D.1@-1682.31,270.47 ; v5(-1722.64,647.64) v5@-1716.73,641.73 ; v5(-1722.64,698.82) v5@-1720.67,700.79 ; v5@-1722.64,700.79 v5@-1720.67,700.79 ; -1722.64,720.47 R419C.1@-1682.31,720.47 ; v5(-1722.64,1097.64) v5@-1716.73,1091.73 ; v5(-1722.64,1148.82) v5@-1720.67,1150.79 ; v5@-1722.64,1150.79 v5@-1720.67,1150.79 ; -1722.64,1170.47 R419B.1@-1682.31,1170.47 ; v5(-1722.64,1547.64) v5@-1716.73,1541.73 ; v5(-1722.64,1598.82) v5@-1720.67,1600.79 ; v5@-1722.64,1600.79 v5@-1720.67,1600.79 ; -1722.64,1620.47 R419A.1@-1682.31,1620.47 ; R418H.1@-1682.31,-1549.21 v5@-1720.67,-1549.21 ; R418G.1@-1682.31,-1099.21 v5@-1720.67,-1099.21 ; R418F.1@-1682.31,-649.21 v5@-1720.67,-649.21 ; R418E.1@-1682.31,-199.21 v5@-1720.67,-199.21 ; R418D.1@-1682.31,250.79 v5@-1720.67,250.79 ; R418C.1@-1682.31,700.79 v5@-1720.67,700.79 ; R418B.1@-1682.31,1150.79 v5@-1720.67,1150.79 ; R418A.1@-1682.31,1600.79 v5@-1720.67,1600.79 ; v1(-1574.41,-162.8) U100.12@-1536.22,-162.8 ; U100.7@-1313.78,-213.98 v1(-1280,-213.98) ; U100.4@-1313.78,-137.2 v1(-1280,-137.2) ; v1(-1275,1737.5) -1275,1722.89 Q10.2@-1274.9,1708.21 ; v1(-1137.5,-1300) C287.2@-1137.5,-1324.41 -1124.28,-1337.63 ccw(c-1094.41,-1307.75) -1094.41,-1350 -1062.5,-1350 -1023.44,-1350 ccw(c-1023.44,-1328.73) -1008.4,-1343.77 R395.1@-990.12,-1325.5 ; v1(-1075,1737.5) -1075,1708.31 Q9.2@-1074.9,1708.21 ; v3(-992.5,-52.1) R392.2@-963.09,-52.1 ; v3(-992.5,-16.3) C285.1@-963.07,-16.3 ; R395.1@-987.5,-1324.41 ccw(c-987.5,-1328.12) -990.11,-1325.48 ccw(c-996.45,-1319.17) R395.1@-987.5,-1319.17 ; v1(-875,1737.5) -875,1708.31 Q8.2@-874.9,1708.21 ; v3(-835.96,-168.31) cw(c-835.96,-194.77) -817.25,-176.06 C282.1@-812.5,-180.81 ; R383.2@-683.07,-98.43 ccw(c-637.92,-53.28) -637.92,-117.13 v3(-582.07,-117.13) ; R386.1@-683.07,68.9 R384.2@-683.07,29.53 -627.22,29.53 cw(c-627.22,-34.32) v3(-582.07,10.83) ; v1(-675,1737.5) -675,1708.31 Q7.2@-674.9,1708.21 ; C271.1@-511.81,-370.08 -507.87,-374.02 v3(-452.76,-374.02) ; C272.1@-511.82,291.34 ccw(c-496.06,291.34) -496.06,275.59 v6(-393.7,275.59) ; Q6.2@-475,1708.31 v1(-475,1737.5) ; C264.2@-468.75,-1461.91 R377.2@-418.75,-1461.91 -393.75,-1461.91 ; C270.1@-395.67,-261.81 ccw(c-381.89,-261.81) -381.89,-275.59 v3(-354.33,-275.59) C269.2@-354.33,-242.13 ; -393.75,-1537.5 -393.75,-1461.91 ; v3(-393.7,-39.37) C259.1@-344.39,9.94 ; R165.1@-368.75,-1461.91 -393.75,-1461.91 ; R165.1@-367.5,-1462.5 -342.5,-1462.5 -342.5,-1433.75 ; C259.1@-348.43,0 cw(c-334.16,0) C259.1@-344.39,9.94 ; C265.1@-314.96,242.13 C255.1@-236.22,242.13 ; C256.1@-268.16,-762.5 C256.1@-266.02,-762.5 ; v6(-196.85,-196.85) C240.1@-151.57,-196.85 ; C251.1@-196.85,33.46 cw(c-182.59,19.2) -182.59,39.37 v3(-157.48,39.37) -157.48,78.74 v3(-157.48,118.11) ; C237.1@-145.67,-78.74 -157.48,-66.93 v3(-157.48,-39.37) -157.48,-11.81 C238.1@-145.67,0 ; C225.1@0,-25.59 -6.25,-19.34 -6.25,19.34 C226.1@0,25.59 ; C209.2@24.41,1062.5 48.99,1037.92 ccw(c50,1038.93) v4(50,1037.5) ; C208.1@24.41,1112.5 ccw(c24.41,1113.93) C208.1@25.42,1112.92 ; C208.1@25.42,1112.92 v4(50,1137.5) ; v3(39.37,0) C219.2@39.37,7.7 ; C216.1@75,-886.91 C201.1@150,-886.91 ; C182.1@143.7,275.59 ccw(c143.7,289.37) 157.48,289.37 v3(157.48,314.96) 157.48,340.55 ccw(c143.7,340.55) C183.1@143.7,354.33 ; C177.2@158.46,511.81 v3(196.85,511.81) ; C168.1@295.28,157.48 301.04,163.25 ccw(c267.44,196.85) v3(314.96,196.85) ; C171.1@309.06,-78.74 C171.1@309.06,-72.83 ; C152.2@563.78,-1320.23 C157.1@563.78,-1270.69 ; C140.1@1486.91,1312.5 v1(1486.91,1331.21) v1(1486.91,1368.94) R342.1@1486.91,1387.5 ; R336.2@1675,1111.91 v1(1711.57,1111.91) v1(1737.5,1111.91) R329.2@1775,1111.91 ; v2(3006.25,-1112.5) cw(c3007.68,-1113.93) 3007.68,-1111.91 R293.2@3043.75,-1111.91 ; v2(3006.25,175) cw(c3007.68,173.57) 3007.68,175.59 R294.2@3043.75,175.59 ; v2(-1825,-1500) cw(c-1851.52,-1473.48) -1878.03,-1500 ccw(c-1851.52,-1473.48) v2(-1825,-1500) ; v2(-1825,-1500) cw(c-1862.5,-1500) v7(-1862.5,-1537.5) ccw(c-1862.5,-1500) v2(-1825,-1500) ; v2(-1825,-1500) cw(c-1851.52,-1526.52) -1825,-1553.03 ccw(c-1851.52,-1526.52) v2(-1825,-1500) ; v2(-1825,-1500) cw(c-1825,-1462.5) v7(-1862.5,-1462.5) ccw(c-1825,-1462.5) v2(-1825,-1500) ; v2(-1825,-1500) cw(c-1798.48,-1473.48) -1825,-1446.97 ccw(c-1798.48,-1473.48) v2(-1825,-1500) ; v2(-1825,-1500) cw(c-1825,-1537.5) v7(-1787.5,-1537.5) ccw(c-1825,-1537.5) v2(-1825,-1500) ; v2(-1825,-1500) cw(c-1798.48,-1526.52) -1771.97,-1500 ccw(c-1798.48,-1526.52) v2(-1825,-1500) ; v2(-1825,-1500) cw(c-1787.5,-1500) v7(-1787.5,-1462.5) ccw(c-1787.5,-1500) v2(-1825,-1500) ; v2(-1825,-1050) cw(c-1862.5,-1050) v7(-1862.5,-1087.5) ccw(c-1862.5,-1050) v2(-1825,-1050) ; v2(-1825,-1050) cw(c-1851.52,-1023.48) -1878.03,-1050 ccw(c-1851.52,-1023.48) v2(-1825,-1050) ; v2(-1825,-1050) cw(c-1851.52,-1076.52) -1825,-1103.03 ccw(c-1851.52,-1076.52) v2(-1825,-1050) ; v2(-1825,-1050) cw(c-1825,-1012.5) v7(-1862.5,-1012.5) ccw(c-1825,-1012.5) v2(-1825,-1050) ; v2(-1825,-1050) cw(c-1798.48,-1023.48) -1825,-996.97 ccw(c-1798.48,-1023.48) v2(-1825,-1050) ; v2(-1825,-1050) cw(c-1825,-1087.5) v7(-1787.5,-1087.5) ccw(c-1825,-1087.5) v2(-1825,-1050) ; v2(-1825,-1050) cw(c-1798.48,-1076.52) -1771.97,-1050 ccw(c-1798.48,-1076.52) v2(-1825,-1050) ; v2(-1825,-1050) cw(c-1787.5,-1050) v7(-1787.5,-1012.5) ccw(c-1787.5,-1050) v2(-1825,-1050) ; v2(-1825,-600) cw(c-1851.52,-573.48) -1878.03,-600 ccw(c-1851.52,-573.48) v2(-1825,-600) ; v2(-1825,-600) cw(c-1862.5,-600) v7(-1862.5,-637.5) ccw(c-1862.5,-600) v2(-1825,-600) ; v2(-1825,-600) cw(c-1851.52,-626.52) -1825,-653.03 ccw(c-1851.52,-626.52) v2(-1825,-600) ; v2(-1825,-600) cw(c-1825,-562.5) v7(-1862.5,-562.5) ccw(c-1825,-562.5) v2(-1825,-600) ; v2(-1825,-600) cw(c-1798.48,-573.48) -1825,-546.97 ccw(c-1798.48,-573.48) v2(-1825,-600) ; v2(-1825,-600) cw(c-1825,-637.5) v7(-1787.5,-637.5) ccw(c-1825,-637.5) v2(-1825,-600) ; v2(-1825,-600) cw(c-1798.48,-626.52) -1771.97,-600 ccw(c-1798.48,-626.52) v2(-1825,-600) ; v2(-1825,-600) cw(c-1787.5,-600) v7(-1787.5,-562.5) ccw(c-1787.5,-600) v2(-1825,-600) ; v2(-1825,-150) cw(c-1862.5,-150) v7(-1862.5,-187.5) ccw(c-1862.5,-150) v2(-1825,-150) ; v2(-1825,-150) cw(c-1851.52,-123.48) -1878.03,-150 ccw(c-1851.52,-123.48) v2(-1825,-150) ; v2(-1825,-150) cw(c-1851.52,-176.52) -1825,-203.03 ccw(c-1851.52,-176.52) v2(-1825,-150) ; v2(-1825,-150) cw(c-1825,-112.5) v7(-1862.5,-112.5) ccw(c-1825,-112.5) v2(-1825,-150) ; v2(-1825,-150) cw(c-1798.48,-123.48) -1825,-96.97 ccw(c-1798.48,-123.48) v2(-1825,-150) ; v2(-1825,-150) cw(c-1825,-187.5) v7(-1787.5,-187.5) ccw(c-1825,-187.5) v2(-1825,-150) ; v2(-1825,-150) cw(c-1798.48,-176.52) -1771.97,-150 ccw(c-1798.48,-176.52) v2(-1825,-150) ; v2(-1825,-150) cw(c-1787.5,-150) v7(-1787.5,-112.5) ccw(c-1787.5,-150) v2(-1825,-150) ; v2(-1825,300) cw(c-1862.5,300) v7(-1862.5,262.5) ccw(c-1862.5,300) v2(-1825,300) ; v2(-1825,300) cw(c-1851.52,326.52) -1878.03,300 ccw(c-1851.52,326.52) v2(-1825,300) ; v2(-1825,300) cw(c-1851.52,273.48) -1825,246.97 ccw(c-1851.52,273.48) v2(-1825,300) ; v2(-1825,300) cw(c-1825,337.5) v7(-1862.5,337.5) ccw(c-1825,337.5) v2(-1825,300) ; v2(-1825,300) cw(c-1798.48,326.52) -1825,353.03 ccw(c-1798.48,326.52) v2(-1825,300) ; v2(-1825,300) cw(c-1825,262.5) v7(-1787.5,262.5) ccw(c-1825,262.5) v2(-1825,300) ; v2(-1825,300) cw(c-1798.48,273.48) -1771.97,300 ccw(c-1798.48,273.48) v2(-1825,300) ; v2(-1825,300) cw(c-1787.5,300) v7(-1787.5,337.5) ccw(c-1787.5,300) v2(-1825,300) ; v2(-1825,750) cw(c-1862.5,750) v7(-1862.5,712.5) ccw(c-1862.5,750) v2(-1825,750) ; v2(-1825,750) cw(c-1851.52,776.52) -1878.03,750 ccw(c-1851.52,776.52) v2(-1825,750) ; v2(-1825,750) cw(c-1851.52,723.48) -1825,696.97 ccw(c-1851.52,723.48) v2(-1825,750) ; v2(-1825,750) cw(c-1825,787.5) v7(-1862.5,787.5) ccw(c-1825,787.5) v2(-1825,750) ; v2(-1825,750) cw(c-1798.48,776.52) -1825,803.03 ccw(c-1798.48,776.52) v2(-1825,750) ; v2(-1825,750) cw(c-1825,712.5) v7(-1787.5,712.5) ccw(c-1825,712.5) v2(-1825,750) ; v2(-1825,750) cw(c-1798.48,723.48) -1771.97,750 ccw(c-1798.48,723.48) v2(-1825,750) ; v2(-1825,750) cw(c-1787.5,750) v7(-1787.5,787.5) ccw(c-1787.5,750) v2(-1825,750) ; v2(-1825,1200) cw(c-1851.52,1226.52) -1878.03,1200 ccw(c-1851.52,1226.52) v2(-1825,1200) ; v2(-1825,1200) cw(c-1862.5,1200) v7(-1862.5,1162.5) ccw(c-1862.5,1200) v2(-1825,1200) ; v2(-1825,1200) cw(c-1851.52,1173.48) -1825,1146.97 ccw(c-1851.52,1173.48) v2(-1825,1200) ; v2(-1825,1200) cw(c-1825,1237.5) v7(-1862.5,1237.5) ccw(c-1825,1237.5) v2(-1825,1200) ; v2(-1825,1200) cw(c-1798.48,1226.52) -1825,1253.03 ccw(c-1798.48,1226.52) v2(-1825,1200) ; v2(-1825,1200) cw(c-1825,1162.5) v7(-1787.5,1162.5) ccw(c-1825,1162.5) v2(-1825,1200) ; v2(-1825,1200) cw(c-1798.48,1173.48) -1771.97,1200 ccw(c-1798.48,1173.48) v2(-1825,1200) ; v2(-1825,1200) cw(c-1787.5,1200) v7(-1787.5,1237.5) ccw(c-1787.5,1200) v2(-1825,1200) ; v2(-1825,1650) cw(c-1851.52,1676.52) -1878.03,1650 ccw(c-1851.52,1676.52) v2(-1825,1650) ; v2(-1825,1650) cw(c-1862.5,1650) v7(-1862.5,1612.5) ccw(c-1862.5,1650) v2(-1825,1650) ; v2(-1825,1650) cw(c-1851.52,1623.48) -1825,1596.97 ccw(c-1851.52,1623.48) v2(-1825,1650) ; v2(-1825,1650) cw(c-1825,1687.5) v7(-1862.5,1687.5) ccw(c-1825,1687.5) v2(-1825,1650) ; v2(-1825,1650) cw(c-1798.48,1676.52) -1825,1703.03 ccw(c-1798.48,1676.52) v2(-1825,1650) ; v2(-1825,1650) cw(c-1825,1612.5) v7(-1787.5,1612.5) ccw(c-1825,1612.5) v2(-1825,1650) ; v2(-1825,1650) cw(c-1798.48,1623.48) -1771.97,1650 ccw(c-1798.48,1623.48) v2(-1825,1650) ; v2(-1825,1650) cw(c-1787.5,1650) v7(-1787.5,1687.5) ccw(c-1787.5,1650) v2(-1825,1650) ; C259.1@-344.39,9.94 cw(c-334.16,0) -344.25,10.09 v3(-314.96,39.37) C259.1@-344.39,9.94 ; v1(-1650,-1670) v1(-1650,-1655) -1643.7,-1655 cw(c-1643.7,-1680.61) C288H.2@-1625.59,-1662.5 cw(c-1643.7,-1644.39) -1643.7,-1670 v1(-1650,-1670) ; v1(-1650,-1345) v1(-1650,-1330) -1633.09,-1330 cw(c-1633.09,-1337.5) C289H.2@-1625.59,-1337.5 cw(c-1633.09,-1337.5) -1633.09,-1345 v1(-1650,-1345) ; v1(-1650,-1220) v1(-1650,-1205) -1643.7,-1205 cw(c-1643.7,-1230.61) C288G.2@-1625.59,-1212.5 cw(c-1643.7,-1194.39) -1643.7,-1220 v1(-1650,-1220) ; v1(-1650,-895) v1(-1650,-880) -1633.09,-880 cw(c-1633.09,-887.5) C289G.2@-1625.59,-887.5 cw(c-1633.09,-887.5) -1633.09,-895 v1(-1650,-895) ; v1(-1650,-770) v1(-1650,-755) -1643.7,-755 cw(c-1643.7,-780.61) C288F.2@-1625.59,-762.5 cw(c-1643.7,-744.39) -1643.7,-770 v1(-1650,-770) ; v1(-1650,-445) v1(-1650,-430) -1633.09,-430 cw(c-1633.09,-437.5) C289F.2@-1625.59,-437.5 cw(c-1633.09,-437.5) -1633.09,-445 v1(-1650,-445) ; v1(-1650,-320) v1(-1650,-305) -1643.7,-305 cw(c-1643.7,-330.61) C288E.2@-1625.59,-312.5 cw(c-1643.7,-294.39) -1643.7,-320 v1(-1650,-320) ; v1(-1650,5) v1(-1650,20) -1633.09,20 cw(c-1633.09,12.5) C289E.2@-1625.59,12.5 cw(c-1633.09,12.5) -1633.09,5 v1(-1650,5) ; v1(-1650,130) v1(-1650,145) -1643.7,145 cw(c-1643.7,119.39) C288D.2@-1625.59,137.5 cw(c-1643.7,155.61) -1643.7,130 v1(-1650,130) ; v1(-1650,455) v1(-1650,470) -1633.09,470 cw(c-1633.09,462.5) C289D.2@-1625.59,462.5 cw(c-1633.09,462.5) -1633.09,455 v1(-1650,455) ; v1(-1650,580) v1(-1650,595) -1643.7,595 cw(c-1643.7,569.39) C288C.2@-1625.59,587.5 cw(c-1643.7,605.61) -1643.7,580 v1(-1650,580) ; v1(-1650,905) v1(-1650,920) -1633.09,920 cw(c-1633.09,912.5) C289C.2@-1625.59,912.5 cw(c-1633.09,912.5) -1633.09,905 v1(-1650,905) ; v1(-1650,1030) v1(-1650,1045) -1643.7,1045 cw(c-1643.7,1019.39) C288B.2@-1625.59,1037.5 cw(c-1643.7,1055.61) -1643.7,1030 v1(-1650,1030) ; v1(-1650,1355) v1(-1650,1370) -1633.09,1370 cw(c-1633.09,1362.5) C289B.2@-1625.59,1362.5 cw(c-1633.09,1362.5) -1633.09,1355 v1(-1650,1355) ; v1(-1650,1480) v1(-1650,1495) -1643.7,1495 cw(c-1643.7,1469.39) C288A.2@-1625.59,1487.5 cw(c-1643.7,1505.61) -1643.7,1480 v1(-1650,1480) ; v1(-1650,1805) v1(-1650,1820) -1633.09,1820 cw(c-1633.09,1812.5) C289A.2@-1625.59,1812.5 cw(c-1633.09,1812.5) -1633.09,1805 v1(-1650,1805)
  Bottom Layer w12: v1(1902.5,1227.5) v1(1917.5,1227.5) 1925,1227.5 ; v1(1902.5,1472.5) v1(1917.5,1472.5) v1(1932.5,1472.5) v1(1947.5,1472.5) ; C126.2@1925,1199.11 1925,1227.5 ; v1(1947.5,1227.5) v1(1932.5,1227.5) 1925,1227.5
  Bottom Layer w15: U99.5@-1062.5,-1387.4 -1062.5,-1350 U99.2@-1062.5,-1312.6 ; v4(-150,975) C236.1@-125.59,975 ; v4(-100,775) C241.2@-100,811.61 ; R295.1@2454.04,1633.12 cw(c2454.04,1624.66) 2462.5,1624.66 v1(2462.5,1588.68)
  Bottom Layer w15.98: U98.4@268.01,1162.5 v3(324.65,1162.5)
  Bottom Layer w16: C149.1@600.59,1112.5 C150.1@600.59,1162.5 ; C124.1@1950,-808.46 cw(c1969.01,-827.47) 1969.01,-800.59 R314.1@2000,-800.59 v4(2044.47,-800.59) ccw(c2044.47,-748.76) 2081.13,-785.41 C119.1@2087.5,-779.04 ; C125.1@1950,-608.46 cw(c1969.01,-627.47) 1969.01,-600.59 R315.1@2000,-600.59 cw(c2002.14,-602.73) 2002.14,-599.7 v4(2044.47,-599.7) ccw(c2044.47,-545.73) 2082.64,-583.9 C118.1@2087.5,-579.04
  Bottom Layer w20: C228.1@-200,1374.41 -200,1380.06 v10(-159.06,1380.06) ; C165.2@392.72,511.81 457.17,511.81 cw(c457.17,494.1) C155.2@469.69,506.62 ; v3(420.96,775) C161.1@420.96,812.5 v3(420.96,926.77) ; R341.1@1562.5,1588.09 R340.1@1600,1588.09 ; C136.1@1713.39,-812.5 v6(1750,-812.5) ; C137.2@1713.39,-612.5 v6(1750,-612.5) ; R331.2@1725,1588.09 v2(1725,1615) ; C155.2@469.69,506.62 460.79,494.25 460.63,468.63 ccw(c480.63,468.5) v3(460.63,468.5) 460.63,433.07 ccw(c464.57,433.07) FR10.1@464.57,429.13 ccw(c464.57,448.82) 484.25,448.82 v3(484.25,468.5) 484.25,494.25 C155.2@473.43,511.81 C155.2@469.69,506.62
  Bottom Layer w25: v5(-1927.36,-1602.36) v5(-1876.18,-1602.36) -1825.27,-1602.36 v5(-1825,-1602.36) -1815.16,-1602.36 -1795.47,-1602.36 -1775.79,-1602.36 v5(-1773.82,-1602.36) -1756.1,-1602.36 v5(-1722.64,-1602.36) v5(-1722.64,-1551.18) -1722.64,-1549.21 -1722.64,-1529.53 v5(-1722.64,-1500) v5(-1722.64,-1448.82) v5(-1722.64,-1397.64) -1736.42,-1397.64 v5(-1773.82,-1397.64) -1795.47,-1397.64 v5(-1825,-1397.64) -1874.21,-1397.64 v5(-1876.18,-1397.64) -1893.9,-1397.64 -1913.58,-1397.64 v5(-1927.36,-1397.64) v5(-1927.36,-1448.82) v5(-1927.36,-1500) -1927.36,-1509.84 v5(-1927.36,-1551.18) v5(-1927.36,-1602.36) ; v5(-1927.36,-1152.36) v5(-1876.18,-1152.36) -1825.27,-1152.36 v5(-1825,-1152.36) -1815.16,-1152.36 -1795.47,-1152.36 -1775.79,-1152.36 v5(-1773.82,-1152.36) -1756.1,-1152.36 v5(-1722.64,-1152.36) v5(-1722.64,-1101.18) -1722.64,-1099.21 -1722.64,-1079.53 v5(-1722.64,-1050) v5(-1722.64,-998.82) v5(-1722.64,-947.64) -1736.42,-947.64 v5(-1773.82,-947.64) -1795.47,-947.64 v5(-1825,-947.64) -1874.21,-947.64 v5(-1876.18,-947.64) -1893.9,-947.64 -1913.58,-947.64 v5(-1927.36,-947.64) v5(-1927.36,-998.82) v5(-1927.36,-1050) -1927.36,-1059.84 v5(-1927.36,-1101.18) v5(-1927.36,-1152.36) ; v5(-1927.36,-702.36) v5(-1876.18,-702.36) -1825.27,-702.36 v5(-1825,-702.36) -1815.16,-702.36 -1795.47,-702.36 -1775.79,-702.36 v5(-1773.82,-702.36) -1756.1,-702.36 v5(-1722.64,-702.36) v5(-1722.64,-651.18) -1722.64,-649.21 -1722.64,-629.53 v5(-1722.64,-600) v5(-1722.64,-548.82) v5(-1722.64,-497.64) -1736.42,-497.64 v5(-1773.82,-497.64) -1795.47,-497.64 v5(-1825,-497.64) -1874.21,-497.64 v5(-1876.18,-497.64) -1893.9,-497.64 -1913.58,-497.64 v5(-1927.36,-497.64) v5(-1927.36,-548.82) v5(-1927.36,-600) -1927.36,-609.84 v5(-1927.36,-651.18) v5(-1927.36,-702.36) ; v5(-1927.36,-252.36) v5(-1876.18,-252.36) -1825.27,-252.36 v5(-1825,-252.36) -1815.16,-252.36 -1795.47,-252.36 -1775.79,-252.36 v5(-1773.82,-252.36) -1756.1,-252.36 v5(-1722.64,-252.36) v5(-1722.64,-201.18) -1722.64,-199.21 -1722.64,-179.53 v5(-1722.64,-150) v5(-1722.64,-98.82) v5(-1722.64,-47.64) -1736.42,-47.64 v5(-1773.82,-47.64) -1795.47,-47.64 v5(-1825,-47.64) -1874.21,-47.64 v5(-1876.18,-47.64) -1893.9,-47.64 -1913.58,-47.64 v5(-1927.36,-47.64) v5(-1927.36,-98.82) v5(-1927.36,-150) -1927.36,-159.84 v5(-1927.36,-201.18) v5(-1927.36,-252.36) ; v5(-1927.36,197.64) v5(-1876.18,197.64) -1825.27,197.64 v5(-1825,197.64) -1815.16,197.64 -1795.47,197.64 -1775.79,197.64 v5(-1773.82,197.64) -1756.1,197.64 v5(-1722.64,197.64) v5(-1722.64,248.82) -1722.64,250.79 -1722.64,270.47 v5(-1722.64,300) v5(-1722.64,351.18) v5(-1722.64,402.36) -1736.42,402.36 v5(-1773.82,402.36) -1795.47,402.36 v5(-1825,402.36) -1874.21,402.36 v5(-1876.18,402.36) -1893.9,402.36 -1913.58,402.36 v5(-1927.36,402.36) v5(-1927.36,351.18) v5(-1927.36,300) -1927.36,290.16 v5(-1927.36,248.82) v5(-1927.36,197.64) ; v5(-1927.36,647.64) v5(-1876.18,647.64) -1825.27,647.64 v5(-1825,647.64) -1815.16,647.64 -1795.47,647.64 -1775.79,647.64 v5(-1773.82,647.64) -1756.1,647.64 v5(-1722.64,647.64) v5(-1722.64,698.82) -1722.64,700.79 -1722.64,720.47 v5(-1722.64,750) v5(-1722.64,801.18) v5(-1722.64,852.36) -1736.42,852.36 v5(-1773.82,852.36) -1795.47,852.36 v5(-1825,852.36) -1874.21,852.36 v5(-1876.18,852.36) -1893.9,852.36 -1913.58,852.36 v5(-1927.36,852.36) v5(-1927.36,801.18) v5(-1927.36,750) -1927.36,740.16 v5(-1927.36,698.82) v5(-1927.36,647.64) ; v5(-1927.36,1097.64) v5(-1876.18,1097.64) -1825.27,1097.64 v5(-1825,1097.64) -1815.16,1097.64 -1795.47,1097.64 -1775.79,1097.64 v5(-1773.82,1097.64) -1756.1,1097.64 v5(-1722.64,1097.64) v5(-1722.64,1148.82) -1722.64,1150.79 -1722.64,1170.47 v5(-1722.64,1200) v5(-1722.64,1251.18) v5(-1722.64,1302.36) -1736.42,1302.36 v5(-1773.82,1302.36) -1795.47,1302.36 v5(-1825,1302.36) -1874.21,1302.36 v5(-1876.18,1302.36) -1893.9,1302.36 -1913.58,1302.36 v5(-1927.36,1302.36) v5(-1927.36,1251.18) v5(-1927.36,1200) -1927.36,1190.16 v5(-1927.36,1148.82) v5(-1927.36,1097.64) ; v5(-1927.36,1547.64) v5(-1876.18,1547.64) -1825.27,1547.64 v5(-1825,1547.64) -1815.16,1547.64 -1795.47,1547.64 -1775.79,1547.64 v5(-1773.82,1547.64) -1756.1,1547.64 v5(-1722.64,1547.64) v5(-1722.64,1598.82) -1722.64,1600.79 -1722.64,1620.47 v5(-1722.64,1650) v5(-1722.64,1701.18) v5(-1722.64,1752.36) -1736.42,1752.36 v5(-1773.82,1752.36) -1795.47,1752.36 v5(-1825,1752.36) -1874.21,1752.36 v5(-1876.18,1752.36) -1893.9,1752.36 -1913.58,1752.36 v5(-1927.36,1752.36) v5(-1927.36,1701.18) v5(-1927.36,1650) -1927.36,1640.16 v5(-1927.36,1598.82) v5(-1927.36,1547.64)
  Bottom Layer w30: v9(2462.5,-806.25) C114.1@2462.5,-757.38 ; v9(2462.5,-606.25) C115.1@2462.5,-557.38
  Bottom Layer w40: C111.2@2589.07,1075.89 FL1.4@2589.07,1135.93
  other v1: -1716.73,-1358.92 -1082.68,-1112.2 -1716.73,-908.92 -1082.68,-767.72 -1013.78,-610.24 -994.09,-590.55 -974.41,-570.87 -954.72,-551.18 -1716.73,-458.92 -1082.68,-433.07 -1716.73,-8.92 -1082.68,226.38 -1716.73,441.08 -1082.68,570.87 -825,850 -775.25,850.06 -750.25,850.06 -725.25,850.06 -700.25,850.06 -650.25,850.06 -1716.73,891.08 -825,900 -775.25,900.06 -700.25,900.06 -650.25,900.06 -825,925 -650.25,925.06 -825,950 -650.25,950.06 -825,975 -775.25,975.06 -700.25,975.06 -650.25,975.06 -825,1025 -775.25,1025.06 -750.25,1025.06 -725.25,1025.06 -700.25,1025.06 -650.25,1025.06 -1082.68,1102.36 1425,1235 1425,1265 -1716.73,1341.08 1425,1437.5 1425,1450 1425,1462.5 -1716.73,1791.08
